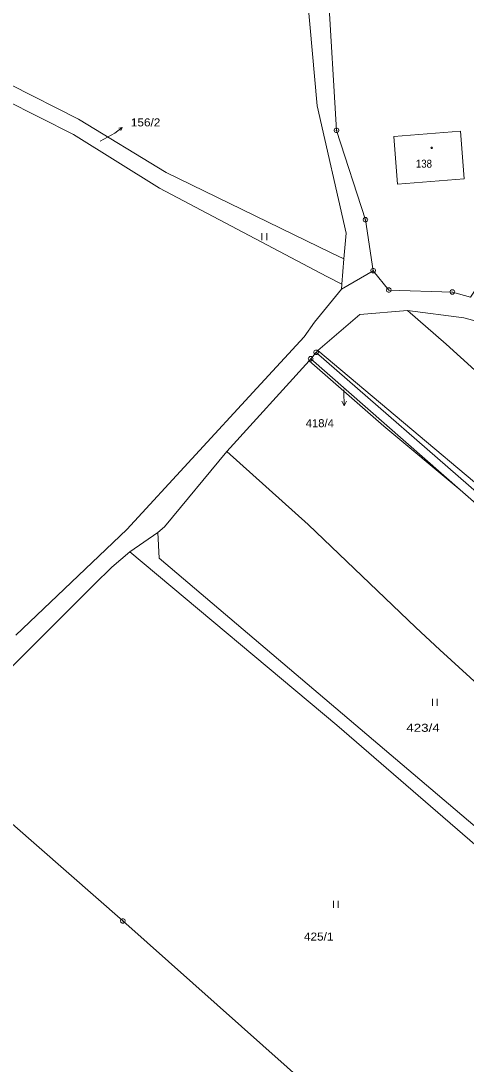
# Model space of a CAD drawing. Extents: x -687390 to -684106, y -954833 to -951648.
# Drawn here: x -686675.9 to -686581.3, y -952815.4 to -952593.8 of the extents above; entities that cross this region are included whole.
import ezdxf
from ezdxf.enums import TextEntityAlignment as Align

# ---------------------------------------------------------------- set-up
doc = ezdxf.new("R2010")
doc.units = 0
doc.header["$LTSCALE"] = 0.68
for name, color, linetype, lineweight in [('1', 7, 'Continuous', 13), ('3', 7, 'Continuous', 13), ('5', 7, 'Continuous', 13), ('7', 7, 'Continuous', 13), ('8', 7, 'Continuous', 13)]:
    doc.layers.add(name, color=color, linetype=linetype, lineweight=lineweight)
doc.layers.add('2', color=7, linetype='Continuous')

msp = doc.modelspace()

# ---------------------------------------------------------------- linework, layer by layer
at = {"layer": '1'}
for p, q in [((-686612.98, -952611.85), (-686615.22, -952586.81)), ((-686664.7, -952617.94), (-686679.26, -952610.56)), ((-686646.42, -952629.3), (-686664.7, -952617.94)), ((-686610.88, -952648.04), (-686646.42, -952629.3)), ((-686609.97, -952643.03), (-686607.29, -952644.33)), ((-686607.29, -952644.33), (-686607.71, -952649.71)), ((-686607.82, -952650.79), (-686601.08, -952646.83)), ((-686610.88, -952648.04), (-686607.71, -952649.71)), ((-686607.71, -952649.71), (-686607.82, -952650.79)), ((-686593.81, -952655.27), (-686585.59, -952662.44)), ((-686585.59, -952662.44), (-686562.27, -952683.54)), ((-686613.19, -952664.18), (-686529.1, -952737.61)), ((-686612.84, -952663.77), (-686545.12, -952720.73)), ((-686632.17, -952685.27), (-686614.69, -952665.98)), ((-686614.69, -952665.98), (-686598.83, -952679.82)), ((-686598.83, -952679.82), (-686582.57, -952693.38)), ((-686632.17, -952685.27), (-686645.37, -952701.24)), ((-686614.89, -952700.76), (-686632.17, -952685.27)), ((-686676.92, -952724.22), (-686653.39, -952701.81)), ((-686646.83, -952702.47), (-686645.37, -952701.24)), ((-686614.89, -952700.76), (-686591.98, -952722.6)), ((-686652.75, -952706.57), (-686656.59, -952709.81)), ((-686660.3, -952713.48), (-686656.59, -952709.81)), ((-686695.55, -952748.71), (-686660.3, -952713.48)), ((-686586.94, -952727.34), (-686591.98, -952722.6)), ((-686530.65, -952778.73), (-686586.94, -952727.34))]:
    msp.add_line(p, q, dxfattribs=at)
for points in [[(-686492.17, -952518.13), (-686580.4, -952652.47), (-686584.25, -952651.36)], [(-686601.08, -952646.83), (-686602.71, -952636.02), (-686608.85, -952617.04), (-686610.66, -952587.43), (-686612.97, -952578.45)], [(-686699.62, -952598.33), (-686678.18, -952607.31), (-686663.65, -952614.62), (-686645, -952625.95), (-686609.97, -952643.03)], [(-686612.98, -952611.85), (-686606.77, -952638.87), (-686607.29, -952644.33)], [(-686601.08, -952646.83), (-686597.73, -952650.96), (-686584.25, -952651.36)], [(-686653.39, -952701.81), (-686625.8, -952671.78), (-686615.72, -952660.86), (-686613.53, -952657.78), (-686607.82, -952650.79)], [(-686612.84, -952663.77), (-686603.93, -952656.15), (-686593.81, -952655.27)], [(-686593.81, -952655.27), (-686581.83, -952656.84), (-686553.46, -952664.51)], [(-686614.69, -952665.98), (-686614.33, -952665.54), (-686613.19, -952664.18), (-686612.84, -952663.77)], [(-686511, -952756.1), (-686582.57, -952693.38), (-686614.33, -952665.54)], [(-686652.75, -952706.57), (-686646.83, -952702.47), (-686646.49, -952707.88)], [(-686652.75, -952706.57), (-686608.8, -952743.34), (-686551.22, -952793.14)], [(-686646.49, -952707.88), (-686543.29, -952795.55), (-686519.6, -952815.68)], [(-686695.55, -952748.71), (-686654.22, -952784.95), (-686599.33, -952833.8), (-686574.97, -952856.02)]]:
    msp.add_lwpolyline(points, dxfattribs=at)
msp.add_lwpolyline([(-686596.69, -952618.3), (-686582.55, -952617.19), (-686581.75, -952627.31), (-686595.92, -952628.44)], close=True, dxfattribs=at)
at = {"layer": '3'}
for p, q in [((-686624.68, -952638.88), (-686624.68, -952640.38)), ((-686623.68, -952640.38), (-686623.68, -952638.88)), ((-686588.47, -952737.76), (-686588.47, -952739.26)), ((-686587.47, -952739.26), (-686587.47, -952737.76)), ((-686609.51, -952780.66), (-686609.51, -952782.16)), ((-686608.51, -952782.16), (-686608.51, -952780.66))]:
    msp.add_line(p, q, dxfattribs=at)
at = {"layer": '5'}
msp.add_lwpolyline([(-686588.58, -952620.58), (-686588.49, -952620.73), (-686588.58, -952620.88), (-686588.76, -952620.88), (-686588.85, -952620.73), (-686588.76, -952620.58)], close=True, dxfattribs=at)
at = {"layer": '7'}
for p, q in [((-686659.03, -952619.3), (-686655.95, -952617.62)), ((-686654.337, -952616.42), (-686655.95, -952617.62)), ((-686607.28, -952672.13), (-686607.29, -952672.55)), ((-686607.196, -952675.549), (-686607.29, -952672.55))]:
    msp.add_line(p, q, dxfattribs=at)
for points in [[(-686655.075, -952616.551), (-686654.337, -952616.42), (-686654.675, -952617.089)], [(-686606.727, -952674.533), (-686607.196, -952675.549), (-686607.727, -952674.565)]]:
    msp.add_lwpolyline(points, dxfattribs=at)
at = {"layer": '8'}
for p, q in [((-686608.97, -952617.04), (-686608.73, -952617.04)), ((-686602.83, -952636.02), (-686602.59, -952636.02)), ((-686601.2, -952646.83), (-686600.96, -952646.83)), ((-686597.85, -952650.96), (-686597.61, -952650.96)), ((-686584.37, -952651.36), (-686584.13, -952651.36)), ((-686613.31, -952664.18), (-686613.07, -952664.18)), ((-686614.45, -952665.54), (-686614.21, -952665.54)), ((-686654.34, -952784.95), (-686654.1, -952784.95))]:
    msp.add_line(p, q, dxfattribs=at)
for points in [[(-686608.7, -952616.56), (-686608.45, -952616.74), (-686608.35, -952617.03), (-686608.45, -952617.32), (-686608.7, -952617.5), (-686609.01, -952617.5), (-686609.26, -952617.32), (-686609.36, -952617.03), (-686609.26, -952616.74), (-686609.01, -952616.56)], [(-686602.56, -952635.54), (-686602.31, -952635.72), (-686602.21, -952636.01), (-686602.31, -952636.3), (-686602.56, -952636.48), (-686602.87, -952636.48), (-686603.12, -952636.3), (-686603.22, -952636.01), (-686603.12, -952635.72), (-686602.87, -952635.54)], [(-686600.93, -952646.35), (-686600.68, -952646.53), (-686600.58, -952646.82), (-686600.68, -952647.11), (-686600.93, -952647.29), (-686601.24, -952647.29), (-686601.49, -952647.11), (-686601.59, -952646.82), (-686601.49, -952646.53), (-686601.24, -952646.35)], [(-686597.58, -952650.48), (-686597.33, -952650.66), (-686597.23, -952650.95), (-686597.33, -952651.24), (-686597.58, -952651.42), (-686597.89, -952651.42), (-686598.14, -952651.24), (-686598.24, -952650.95), (-686598.14, -952650.66), (-686597.89, -952650.48)], [(-686584.1, -952650.88), (-686583.85, -952651.06), (-686583.75, -952651.35), (-686583.85, -952651.64), (-686584.1, -952651.82), (-686584.41, -952651.82), (-686584.66, -952651.64), (-686584.76, -952651.35), (-686584.66, -952651.06), (-686584.41, -952650.88)], [(-686613.04, -952663.7), (-686612.79, -952663.88), (-686612.69, -952664.17), (-686612.79, -952664.46), (-686613.04, -952664.64), (-686613.35, -952664.64), (-686613.6, -952664.46), (-686613.7, -952664.17), (-686613.6, -952663.88), (-686613.35, -952663.7)], [(-686614.18, -952665.06), (-686613.93, -952665.24), (-686613.83, -952665.53), (-686613.93, -952665.82), (-686614.18, -952666), (-686614.49, -952666), (-686614.74, -952665.82), (-686614.84, -952665.53), (-686614.74, -952665.24), (-686614.49, -952665.06)], [(-686654.07, -952784.47), (-686653.82, -952784.65), (-686653.72, -952784.94), (-686653.82, -952785.23), (-686654.07, -952785.41), (-686654.38, -952785.41), (-686654.63, -952785.23), (-686654.73, -952784.94), (-686654.63, -952784.65), (-686654.38, -952784.47)]]:
    msp.add_lwpolyline(points, close=True, dxfattribs=at)

# ---------------------------------------------------------------- texts
at = {"layer": '2'}
for s, height, width, p in [('156/2', 0.1, 1.1, (-686658.984, -952619.3)), ('138', 1.7, 0.9, (-686591.995, -952624.96)), ('418/4', 0.1, 1.05, (-686607.252, -952672.13)), ('423/4', 1.7, 1.25, (-686594.045, -952744.77)), ('425/1', 1.7, 1.1, (-686615.765, -952789.11))]:
    msp.add_text(s, height=height, dxfattribs=dict(at, width=width)).set_placement(p)
at = {"layer": '7', "width": 1.1}
msp.add_text('156/2', height=1.7, dxfattribs=at).set_placement((-686652.525, -952616.19))
at = {"layer": '7', "width": 1.05}
msp.add_text('418/4', height=1.7, dxfattribs=at).set_placement((-686609.416, -952680.07), align=Align.RIGHT)

doc.saveas('drawing.dxf')
